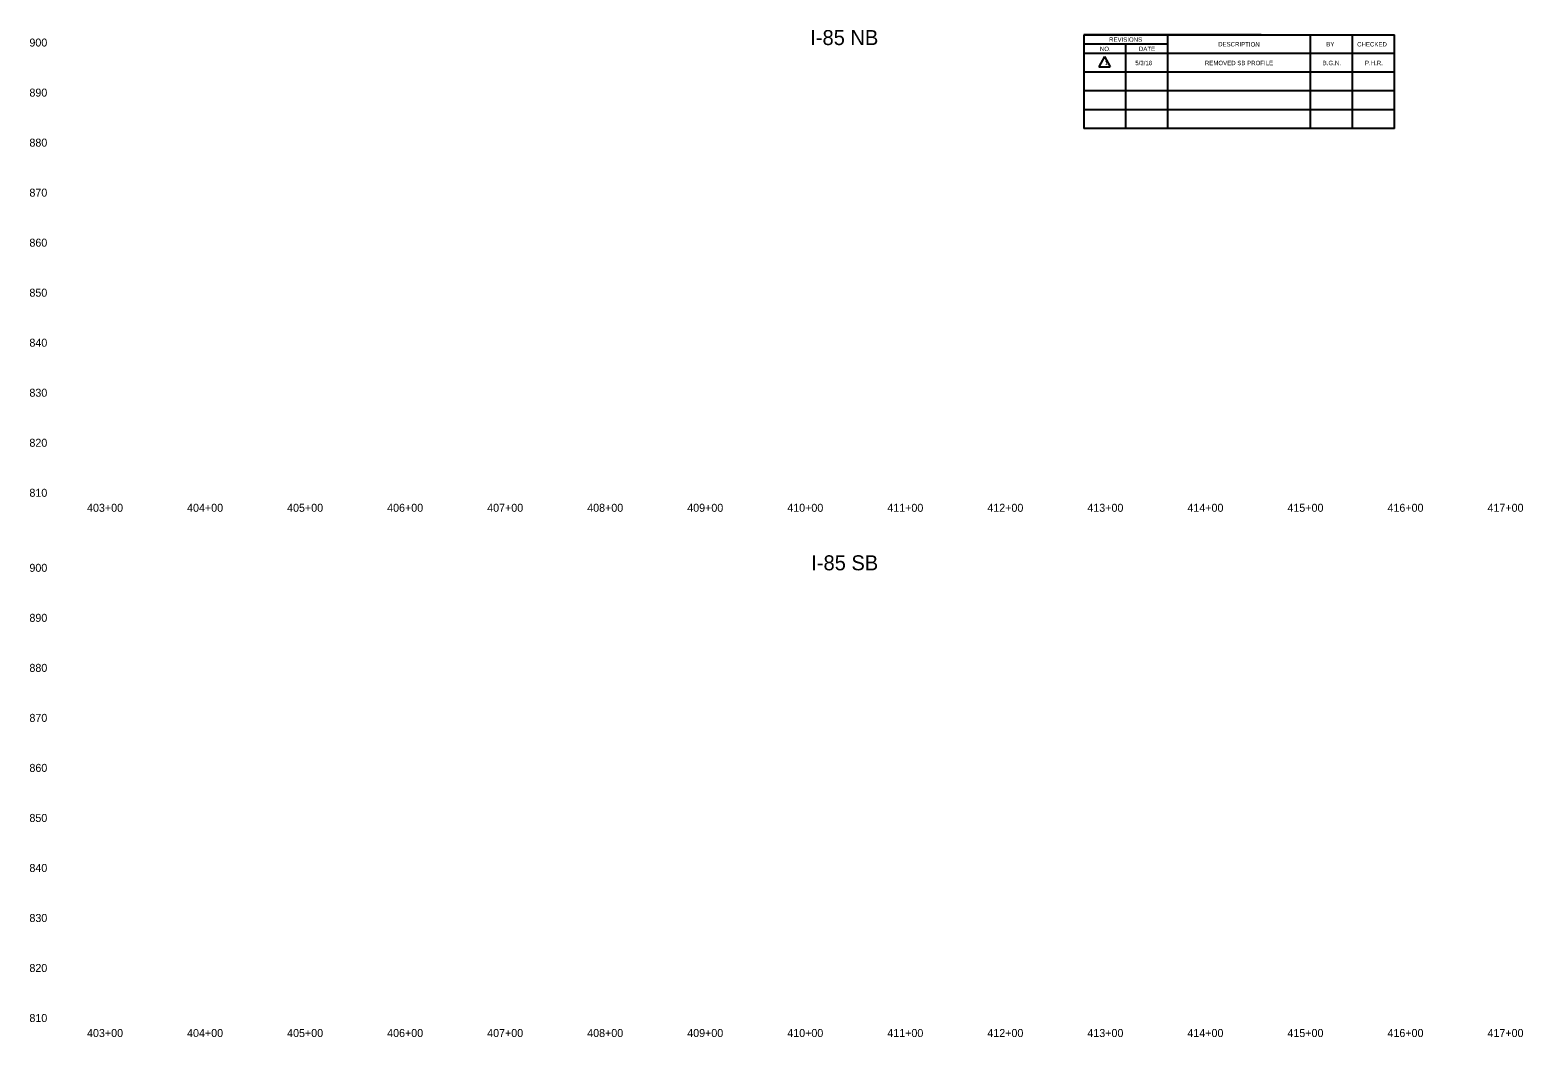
# Model space of a CAD drawing. Extents: x 16992642 to 16995679, y 12627721 to 12628791.
# Drawn here: x 16992642 to 16994134, y 12627721 to 12628728 of the extents above; entities that cross this region are included whole.
import ezdxf

# ---------------------------------------------------------------- set-up
doc = ezdxf.new("R2010")
doc.units = 0
doc.layers.add('Default', color=7, linetype='Continuous')
doc.layers.add('RD_SHT_TX', color=7, linetype='Continuous')

msp = doc.modelspace()

# ---------------------------------------------------------------- linework, layer by layer
at = {"layer": 'RD_SHT_TX'}
for p, q in [((16993695.2, 12628723.3), (16994005.8, 12628723.3)), ((16993872.5, 12628723.3), (16993695.2, 12628723.3)), ((16993695.2, 12628723.3), (16993695.2, 12628629.8)), ((16993779.2, 12628714), (16993695.2, 12628714)), ((16993737.2, 12628629.8), (16993737.2, 12628714)), ((16993779.2, 12628629.8), (16993779.2, 12628723.3)), ((16993921.8, 12628629.8), (16993921.8, 12628723.3)), ((16993963.8, 12628629.8), (16993963.8, 12628723.3)), ((16994005.8, 12628629.8), (16994005.8, 12628723.3)), ((16994005.8, 12628704.6), (16993695.2, 12628704.6)), ((16993715.9, 12628701.6), (16993710.2, 12628691.5)), ((16993715.9, 12628701.6), (16993721.6, 12628691.5)), ((16994005.8, 12628685.9), (16993695.2, 12628685.9)), ((16993710.2, 12628691.5), (16993721.6, 12628691.5)), ((16994005.8, 12628667.2), (16993695.2, 12628667.2)), ((16994005.8, 12628648.5), (16993695.2, 12628648.5)), ((16994005.8, 12628629.8), (16993695.2, 12628629.8))]:
    msp.add_line(p, q, dxfattribs=at)

# ---------------------------------------------------------------- texts
at = {"layer": 'Default'}
for s, p in [('900', (16992641.2, 12628711.6)), ('890', (16992641.2, 12628661.6)), ('880', (16992641.2, 12628611.6)), ('870', (16992641.2, 12628561.6)), ('860', (16992641.2, 12628511.6)), ('850', (16992641.2, 12628461.6)), ('840', (16992641.2, 12628411.6)), ('830', (16992641.2, 12628361.6)), ('820', (16992641.2, 12628311.6)), ('810', (16992641.2, 12628261.6)), ('403+00', (16992698.8, 12628246.6)), ('404+00', (16992798.8, 12628246.6)), ('405+00', (16992898.8, 12628246.6)), ('406+00', (16992998.8, 12628246.6)), ('407+00', (16993098.8, 12628246.6)), ('408+00', (16993198.8, 12628246.6)), ('409+00', (16993298.8, 12628246.6)), ('410+00', (16993398.8, 12628246.6)), ('411+00', (16993498.8, 12628246.6)), ('412+00', (16993598.8, 12628246.6)), ('413+00', (16993698.8, 12628246.6)), ('414+00', (16993798.8, 12628246.6)), ('415+00', (16993898.8, 12628246.6)), ('416+00', (16993998.8, 12628246.6)), ('417+00', (16994098.8, 12628246.6)), ('900', (16992641.2, 12628186.6)), ('890', (16992641.2, 12628136.6)), ('880', (16992641.2, 12628086.6)), ('870', (16992641.2, 12628036.6)), ('860', (16992641.2, 12627986.6)), ('850', (16992641.2, 12627936.6)), ('840', (16992641.2, 12627886.6)), ('830', (16992641.2, 12627836.6)), ('820', (16992641.2, 12627786.6)), ('810', (16992641.2, 12627736.6)), ('403+00', (16992698.8, 12627721.6)), ('404+00', (16992798.8, 12627721.6)), ('405+00', (16992898.8, 12627721.6)), ('406+00', (16992998.8, 12627721.6)), ('407+00', (16993098.8, 12627721.6)), ('408+00', (16993198.8, 12627721.6)), ('409+00', (16993298.8, 12627721.6)), ('410+00', (16993398.8, 12627721.6)), ('411+00', (16993498.8, 12627721.6)), ('412+00', (16993598.8, 12627721.6)), ('413+00', (16993698.8, 12627721.6)), ('414+00', (16993798.8, 12627721.6)), ('415+00', (16993898.8, 12627721.6)), ('416+00', (16993998.8, 12627721.6)), ('417+00', (16994098.8, 12627721.6))]:
    msp.add_text(s, height=8, dxfattribs=at).set_placement(p)
at = {"layer": 'RD_SHT_TX'}
for s, height, p in [('I-85 NB', 15, (16993421.8, 12628713.1)), ('NO.', 4.4, (16993711.3, 12628707.1)), ('REVISIONS', 4.4, (16993720.5, 12628716.4)), ('CHECKED', 4.4, (16993968.5, 12628711.7)), ('1', 4.4, (16993715.9, 12628693.1)), ('5/3/18', 4.4, (16993746.7, 12628693)), ('REMOVED SB PROFILE', 4.4, (16993816.3, 12628693)), ('B.G.N.', 4.4, (16993934.1, 12628693)), ('P.H.R.', 4.4, (16993976.3, 12628693)), ('I-85 SB', 15, (16993422.8, 12628188.1))]:
    msp.add_text(s, height=height, dxfattribs=at).set_placement(p)
for s, height, p in [('DATE', 4.41, (16993750.3, 12628707.1)), ('DESCRIPTION', 4.408, (16993829.5, 12628711.8)), ('BY', 4.41, (16993937.6, 12628711.8))]:
    msp.add_text(s, height=height, rotation=359.7246, dxfattribs=at).set_placement(p)

doc.saveas('drawing.dxf')
